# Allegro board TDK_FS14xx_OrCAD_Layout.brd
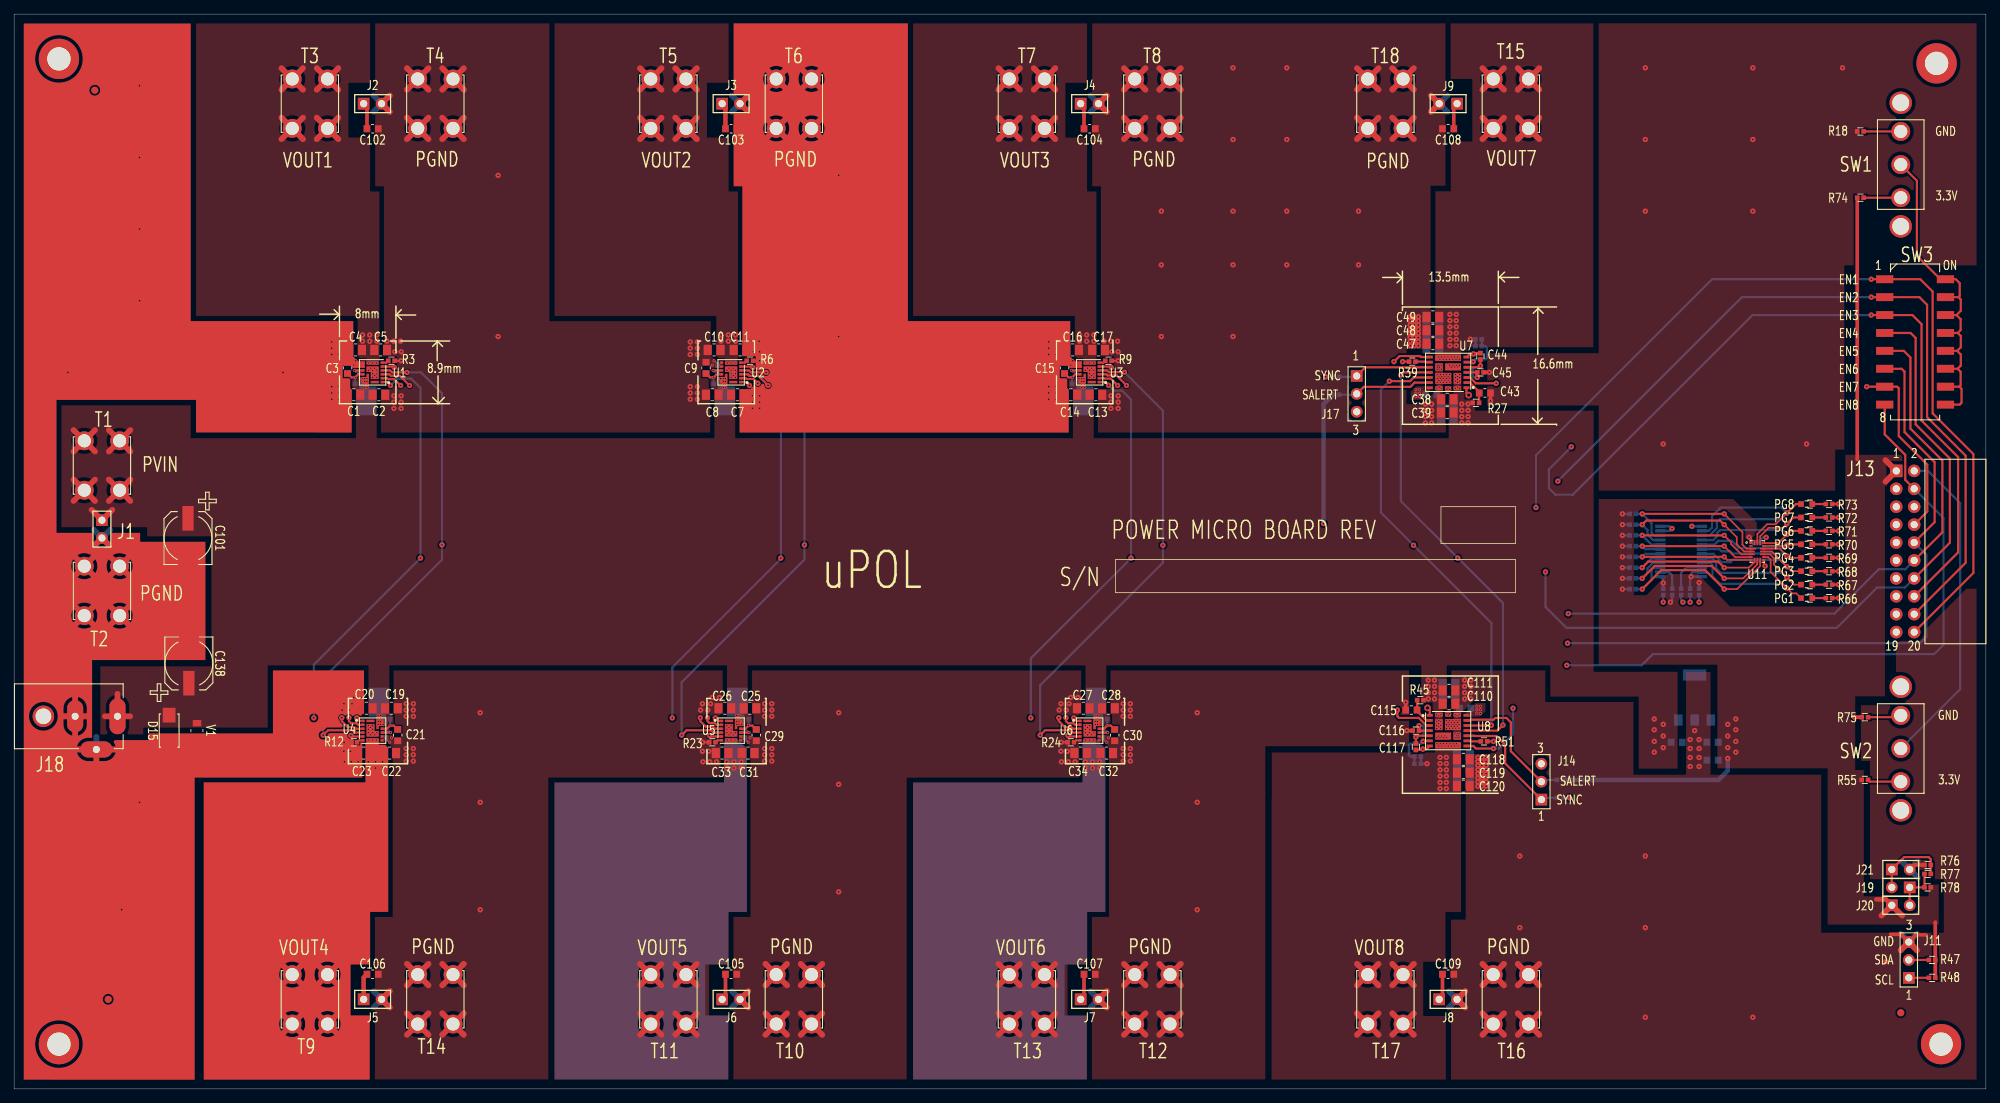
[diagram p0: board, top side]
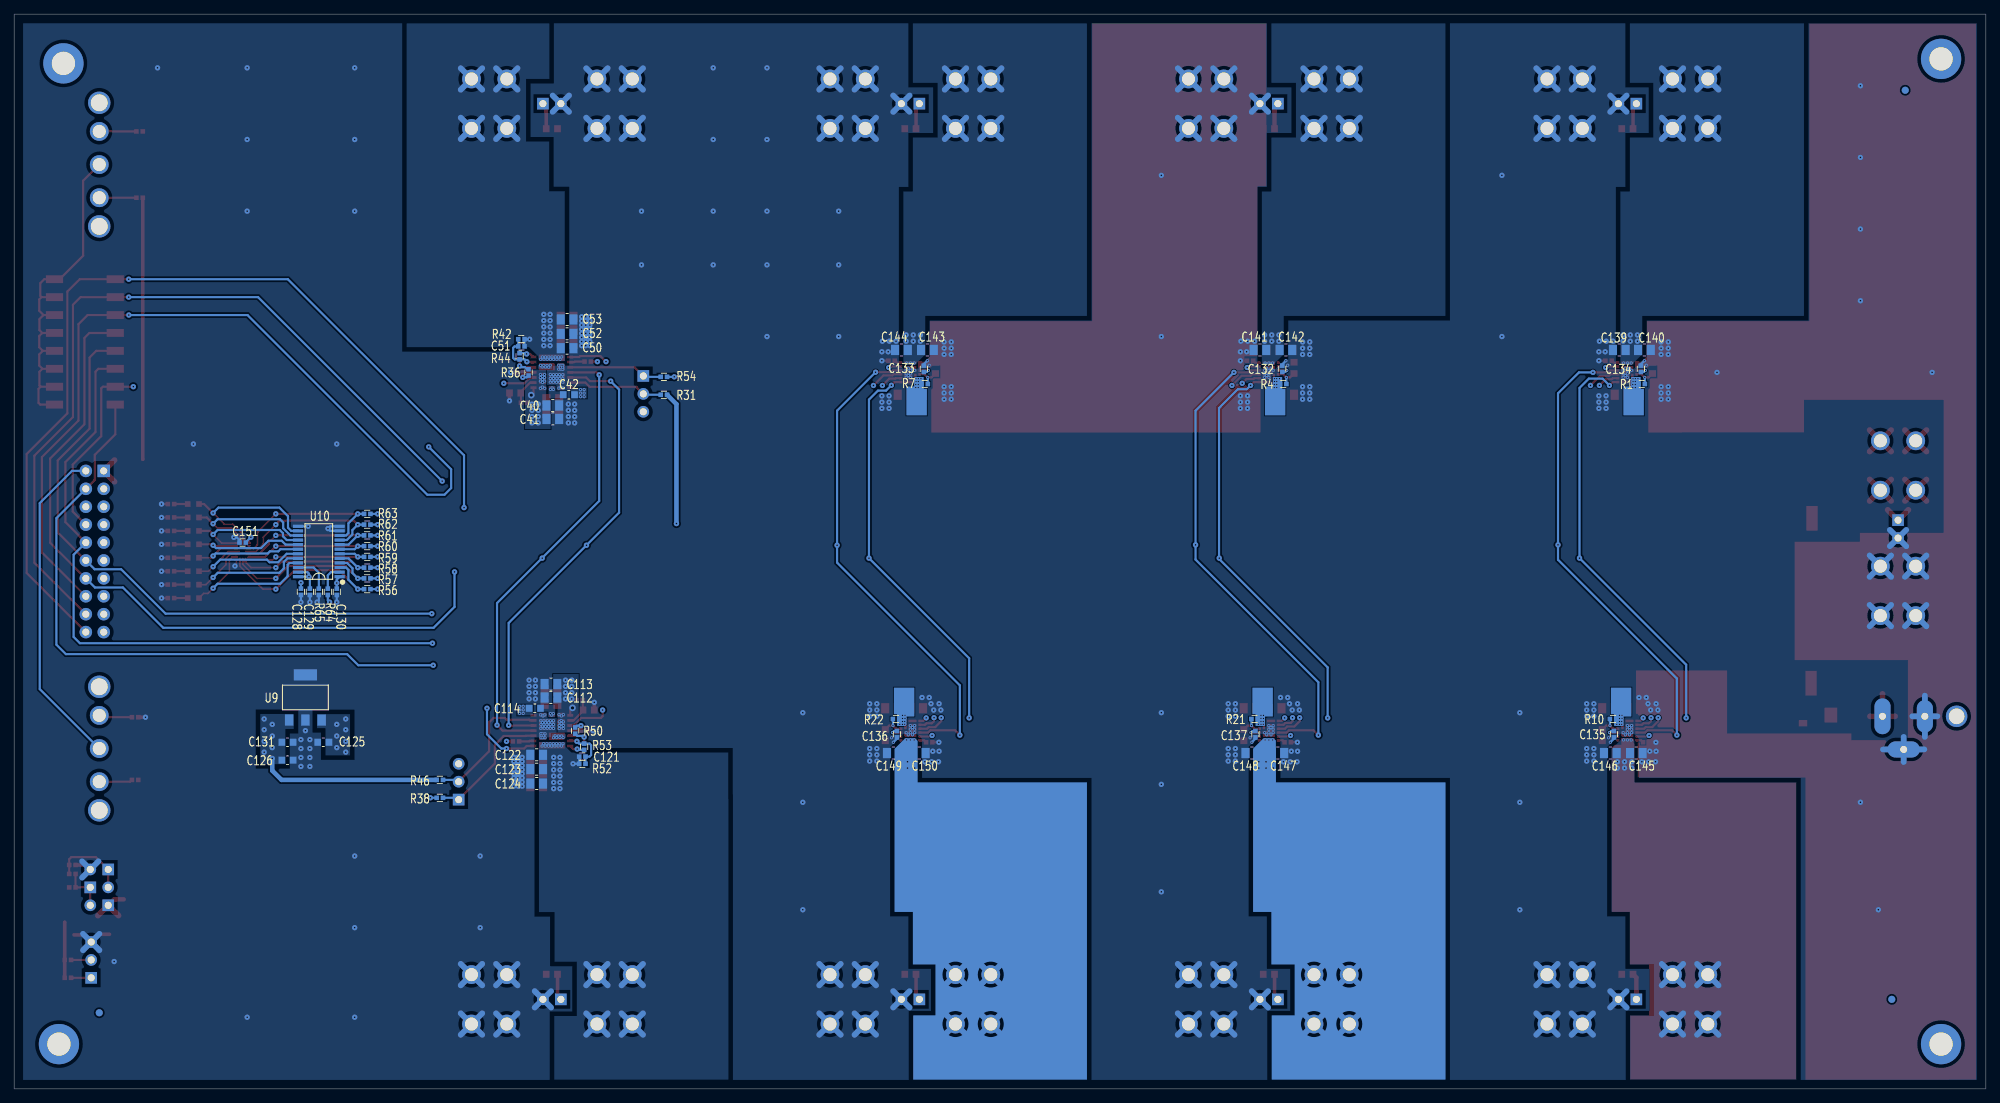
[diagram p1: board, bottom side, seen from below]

Outline 279.4 x 152.4 mm; copper layers: TOP, L2, L3, BOTTOM. Coordinates in mm from the lower left corner of the outline.
Outline path: 0,152.4 0,0 279.4,0 279.4,152.4 0,152.4

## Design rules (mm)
constraint set DEFAULT: min track width 0.305

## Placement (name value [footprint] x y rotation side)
C1  22uF  [0805]  48.13 98.42 0 top
C2  22uF  [0805]  51.69 98.42 180 top
C3  1uF  [0603]  47.24 102.23 270 top
C4  47uF  [0805]  48.39 104.78 180 top
C5  47uF  [0805]  51.94 104.78 0 top
C7  22uF  [0805]  102.49 98.42 180 top
C8  22uF  [0805]  98.93 98.42 0 top
C9  1uF  [0603]  98.04 102.23 270 top
C10  22uF  [0805]  99.19 104.78 180 top
C11  22uF  [0805]  102.87 104.78 0 top
C13  22uF  [0805]  153.29 98.42 180 top
C14  22uF  [0805]  149.73 98.42 0 top
C15  1uF  [0603]  148.84 102.23 270 top
C16  22uF  [0805]  149.99 104.78 180 top
C17  22uF  [0805]  153.67 104.78 0 top
C19  22uF  [0805]  53.47 53.98 180 top
C20  22uF  [0805]  49.91 53.98 0 top
C21  1uF  [0603]  54.36 50.16 90 top
C22  22uF  [0805]  53.21 47.62 0 top
C23  22uF  [0805]  49.53 47.62 180 top
C25  22uF  [0805]  104.27 53.98 180 top
C26  22uF  [0805]  100.71 53.98 0 top
C27  22uF  [0805]  151.51 53.98 0 top
C28  22uF  [0805]  155.07 53.98 180 top
C29  1uF  [0603]  105.16 50.16 90 top
C30  1uF  [0603]  155.96 50.16 90 top
C31  22uF  [0805]  104.01 47.62 0 top
C32  47uF  [0805]  154.81 47.62 0 top
C33  22uF  [0805]  100.33 47.62 180 top
C34  47uF  [0805]  151.13 47.62 180 top
C38  N/S  [0805]  203.07 97.79 0 top
C39  22uF  [0805]  203.07 95.89 0 top
C40  22uF  [0805]  203.07 96.9 0 bottom
C41  22uF  [0805]  203.07 95 0 bottom
C42  2.2uF/16V_N/S  [0603]  200.79 98.42 0 bottom
C43  1uF  [0603]  208.41 98.68 180 top
C44  2.2uF  [0402]  207.77 103.89 270 top
C45  2.2uF  [0402]  207.77 101.6 180 top
C47  N/S  [0805]  201.04 105.66 180 top
C48  N/S  [0805]  201.04 107.57 180 top
C49  N/S  [0805]  201.04 109.47 180 top
C50  N/S  [0805]  201.04 105.03 180 bottom
C51  N/S  [0402]  207.52 105.28 0 bottom
C52  47uF  [0805]  201.04 107.06 180 bottom
C53  47uF  [0805]  201.04 109.09 180 bottom
C101  180uF  [C10_CAP]  24.64 78.11 270 top
C102  1uF  [0603]  50.8 136.14 180 top
C103  1uF  [0603]  101.6 136.14 180 top
C104  1uF  [0603]  152.4 136.14 180 top
C105  1uF  [0603]  101.6 16.26 180 top
C106  1uF  [0603]  50.8 16.26 180 top
C107  1uF  [0603]  152.4 16.26 180 top
C108  1uF  [0603]  203.2 136.14 0 top
C109  1uF  [0603]  203.2 16.26 180 top
C110  N/S  [0805]  203.33 54.61 180 top
C111  22uF  [0805]  203.33 56.52 180 top
C112  22uF  [0805]  203.33 55.5 180 bottom
C113  22uF  [0805]  203.33 57.4 180 bottom
C114  2.2uF/16V_N/S  [0603]  205.61 53.98 180 bottom
C115  1uF  [0603]  197.99 53.72 0 top
C116  2.2uF  [0402]  198.63 50.8 0 top
C117  2.2uF  [0402]  198.63 48.51 90 top
C118  N/S  [0805]  205.36 46.74 0 top
C119  N/S  [0805]  205.36 44.83 0 top
C120  N/S  [0805]  205.36 42.93 0 top
C121  N/S  [0402]  198.88 47.12 180 bottom
C122  N/S  [0805]  205.36 47.37 0 bottom
C123  47uF  [0805]  205.36 45.34 0 bottom
C124  47uF  [0805]  205.36 43.31 0 bottom
C125  1uF  [0603]  235.59 49.15 180 bottom
C126  1uF  [0603]  240.66 46.61 0 bottom
C128  0.1uF  [0402]  238.76 70.48 90 bottom
C129  0.1uF  [0402]  237.49 70.48 90 bottom
C130  0.1uF  [0402]  233.68 70.48 90 bottom
C131  4.7uF  [0603]  240.66 49.15 0 bottom
C132  N/S  [0402]  99.69 102.11 270 bottom
C133  N/S  [0402]  150.5 102.11 270 bottom
C134  N/S  [0402]  48.9 102.11 270 bottom
C135  N/S  [0402]  52.7 50.29 90 bottom
C136  N/S  [0402]  154.31 50.29 90 bottom
C137  N/S  [0402]  103.5 50.29 90 bottom
C138  180uF  [C10_CAP]  24.77 60.33 90 top
C139  47uF  [0805]  51.94 104.78 0 bottom
C140  22uF  [0805]  48.39 104.78 180 bottom
C141  22uF  [0805]  102.87 104.78 0 bottom
C142  22uF  [0805]  99.19 104.78 180 bottom
C143  22uF  [0805]  149.99 104.78 180 bottom
C144  22uF  [0805]  153.67 104.78 0 bottom
C145  N/S  [0805]  49.53 47.62 180 bottom
C146  22uF  [0805]  53.21 47.62 0 bottom
C147  N/S  [0805]  100.33 47.62 180 bottom
C148  22uF  [0805]  104.01 47.62 0 bottom
C149  47uF  [0805]  154.81 47.62 0 bottom
C150  22uF  [0805]  151.13 47.62 180 bottom
C151  1uF  [0402]  247.01 77.47 0 bottom
D1  GREEN  [SML-LX0603]  254 69.6 180 top
D2  GREEN  [SML-LX0603]  254 71.5 180 top
D3  GREEN  [SML-LX0603]  254 73.41 180 top
D4  GREEN  [SML-LX0603]  254 75.31 180 top
D5  GREEN  [SML-LX0603]  254 77.22 180 top
D6  GREEN  [SML-LX0603]  254 79.12 180 top
D7  GREEN  [SML-LX0603]  254 81.03 180 top
D8  GREEN  [SML-LX0603]  254 82.93 180 top
D15  -  [DO-214AC_BI]  21.97 50.8 270 top
J1  -  [HDR1X2]  12.45 79.38 270 top
J2  -  [HDR1X2]  50.8 139.7 0 top
J3  -  [HDR1X2]  101.6 139.7 0 top
J4  -  [HDR1X2]  152.4 139.7 0 top
J5  -  [HDR1X2]  50.8 12.7 0 top
J6  -  [HDR1X2]  101.6 12.7 0 top
J7  -  [HDR1X2]  152.4 12.7 0 top
J8  -  [HDR1X2]  203.2 12.7 0 top
J9  -  [HDR1X2]  203.2 139.7 180 top
J11  -  [HDR1X3]  268.48 18.29 90 top
J13  -  [SSQ-110-02-T-D-RA]  267.97 76.2 270 top
J14  -  [HDR1X3]  216.41 43.56 90 top
J17  -  [HDR1X3]  190.25 98.55 270 top
J18  -  [PJ-058A]  11.65 52.83 270 top
J19  -  [HDR1X2]  267.33 26.04 0 top
J20  -  [HDR1X2]  267.33 28.57 180 top
J21  -  [HDR1X2]  267.33 31.11 0 top
NOREF  -  []  58.9 -20.95 0 top
NOREF#2  -  []  289.56 152.4 0 top
NOREF#3  -  [unnamed#2]  13.34 12.7 0 top
NOREF#4  -  []  0 0 270 top
NOREF#5  -  []  204.53 47.88 0 top
NOREF#6  -  [unnamed#2]  267.33 10.79 0 top
NOREF#7  -  []  99.19 103.89 0 top
NOREF#8  -  [unnamed#2]  272.42 145.41 0 top
NOREF#9  -  []  0 0 0 top
NOREF#10  -  []  0 0 0 top
NOREF#11  -  []  0 0 90 top
NOREF#12  -  []  48.03 103.89 0 top
NOREF#13  -  []  289.56 0 0 top
NOREF#14  -  []  -10.16 0 0 top
NOREF#15  -  []  0 152.4 180 top
NOREF#16  -  []  279.4 0 0 top
NOREF#17  -  []  0 0 0 top
NOREF#18  -  []  279.4 152.4 90 top
NOREF#19  -  [unnamed#2]  6.35 6.35 0 top
NOREF#20  -  []  -300.74 386.97 0 top
NOREF#21  -  []  104.17 48.26 0 top
NOREF#22  -  []  154.37 48.26 0 top
NOREF#23  -  []  149.78 103.89 0 top
NOREF#24  -  []  205.74 104.3 0 top
NOREF#25  -  [unnamed#2]  273.05 6.35 0 top
NOREF#26  -  [unnamed#2]  11.43 141.6 0 top
NOREF#27  -  []  53.64 48.26 0 top
NOREF#28  -  [unnamed#2]  6.35 146.05 0 top
NOREF#29  -  []  0 0 0 top
NOREF#30  -  []  -164.59 -61.47 0 top
NOREF#31  -  []  0 0 90 top
NOREF#32  -  []  -205.49 -126.87 0 top
NOREF#33  -  []  86.08 -39.5 0 top
NOREF#34  -  [unnamed#2]  267.33 10.79 180 bottom
NOREF#35  -  [unnamed#2]  13.34 12.7 180 bottom
NOREF#36  -  [unnamed#2]  11.43 141.6 180 bottom
R1  2.7ohm  [0402]  48.77 99.95 0 bottom
R3  0  [0402]  53.47 103.25 180 top
R4  2.7ohm  [0402]  99.57 99.95 0 bottom
R6  10K  [0402]  104.27 103.25 180 top
R7  2.7ohm  [0402]  150.37 99.95 0 bottom
R9  20K  [0402]  155.07 103.25 180 top
R10  2.7ohm  [0402]  52.83 52.45 180 bottom
R12  49.9K  [0402]  48.13 49.15 0 top
R18  10K  [0402]  261.62 135.76 180 top
R21  2.7ohm  [0402]  103.63 52.45 180 bottom
R22  2.7ohm  [0402]  154.43 52.45 180 bottom
R23  49.9K  [0402]  98.93 49.15 0 top
R24  0  [0402]  149.73 49.15 0 top
R27  2.7ohm  [0402]  207.14 97.28 0 top
R31  4.99K  [0402]  187.32 98.42 180 bottom
R36  0  [0402]  206.5 101.6 270 bottom
R38  10K  [0402]  219.07 41.27 0 bottom
R39  0  [0402]  198.12 103.12 180 top
R42  0  [0402]  207.52 106.3 0 bottom
R44  N/S  [0402]  207.77 103.89 270 bottom
R45  2.7ohm  [0402]  199.26 55.12 180 top
R46  4.99K  [0402]  219.07 43.81 0 bottom
R47  4.99K  [0402]  271.78 18.29 0 top
R48  4.99K  [0402]  271.78 15.75 0 top
R50  0  [0402]  199.9 50.8 90 bottom
R51  0  [0402]  208.28 49.28 0 top
R52  0  [0402]  198.88 46.1 180 bottom
R53  N/S  [0402]  198.63 48.51 90 bottom
R54  10K  [0402]  187.32 100.97 180 bottom
R55  10K  [0402]  262.25 43.81 180 top
R56  49.9K  [0402]  229.36 70.87 180 bottom
R57  49.9K  [0402]  229.36 72.39 180 bottom
R58  49.9K  [0402]  229.36 73.91 0 bottom
R59  49.9K  [0402]  229.36 75.44 180 bottom
R60  49.9K  [0402]  229.36 76.96 180 bottom
R61  49.9K  [0402]  229.36 78.49 180 bottom
R62  49.9K  [0402]  229.36 80.01 0 bottom
R63  49.9K  [0402]  229.36 81.53 180 bottom
R64  10K  [0402]  234.95 70.48 270 bottom
R65  1k  [0402]  236.22 70.48 90 bottom
R66  261  [0402]  257.18 69.6 180 top
R67  261  [0402]  257.18 71.5 180 top
R68  261  [0402]  257.18 73.41 180 top
R69  261  [0402]  257.18 75.31 180 top
R70  261  [0402]  257.18 77.22 180 top
R71  261  [0402]  257.18 79.12 180 top
R72  261  [0402]  257.18 81.03 180 top
R73  261  [0402]  257.18 82.93 180 top
R74  10K  [0402]  261.62 126.36 180 top
R75  10K  [0402]  262.25 52.7 180 top
R76  10K  [0402]  271.14 31.75 180 top
R77  15K  [0402]  271.14 30.48 0 top
R78  15K  [0402]  271.14 28.57 180 top
SW1  -  [1101M1S3CQE2]  267.33 131.06 0 top
SW2  -  [1101M1S3CQE2]  267.33 48.26 0 top
SW3  -  [219-8MST]  269.37 105.92 270 top
T1  -  [7693]  12.45 88.39 0 top
T2  -  [7693]  12.45 70.61 0 top
T3  -  [7693]  41.91 139.7 0 top
T4  -  [7693]  59.69 139.7 0 top
T5  -  [7693]  92.71 139.7 0 top
T6  -  [7693]  110.49 139.7 0 top
T7  -  [7693]  143.51 139.7 0 top
T8  -  [7693]  161.29 139.7 0 top
T9  -  [7693]  41.91 12.7 0 top
T10  -  [7693]  110.49 12.7 0 top
T11  -  [7693]  92.71 12.7 0 top
T12  -  [7693]  161.29 12.7 0 top
T13  -  [7693]  143.51 12.7 0 top
T14  -  [7693]  59.69 12.7 0 top
T15  -  [7693]  212.09 139.7 0 top
T16  -  [7693]  212.09 12.7 0 top
T17  -  [7693]  194.31 12.7 0 top
T18  -  [7693]  194.31 139.7 0 top
U1  -  [FS1406-02_NEW]  50.8 101.6 180 top
U2  -  [FS1406-02_NEW]  101.6 101.6 180 top
U3  -  [FS1406-02_NEW]  152.4 101.6 180 top
U4  -  [FS1406-02_NEW]  50.8 50.8 0 top
U5  -  [FS1406-02_NEW]  101.6 50.8 0 top
U6  -  [FS1406-02_NEW]  152.4 50.8 0 top
U7  -  [FS1412-POD]  203.2 101.6 180 top
U8  -  [FS1412-POD]  203.2 50.8 0 top
U9  -  [SOT223]  238.12 55.5 180 bottom
U10  -  [SOP65P640X120-24N]  236.22 76.2 90 bottom
U11  -  [STQFN20]  247.01 76.2 0 top
V1  -  [AVR]  25.91 50.8 270 top

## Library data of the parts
C1 C2 C4 C5 C7 C8 C10 C11 C13 C14 C16 C17 C19 C20 C22 C23 C25-C28 C31-C34 C38-C41 C47-C50 C52 C53 C110-C113 C118-C120 C122-C124 C139-C150 = 0805
C3 C9 C15 C21 C29 C30 C42 C43 C102-C109 C114 C115 C125 C126 C131 = 0603
C44 C45 C51 C116 C117 C121 C128-C130 C132-C137 C151 R1 R3 R4 R6 R7 R9 R10 R12 R18 R21-R24 R27 R31 R36 R38 R39 R42 R44-R48 R50-R78 = 0402
C101 C138 = C10_CAP
D1-D8 = SML-LX0603
D15 = SMAJ17CA
J1-J9 J19-J21 = HDR1X2
J11 J14 J17 = HDR1X3
J13 = SSQ-110-02-T-D-RA
J18 = PJ-058A
SW1 SW2 = 1101M1S3CQE2
SW3 = 219-8MST
T1-T18 = 7693
U1-U6 = FS1406-02_NEW
U7 = FS1412
U8 = FS1408
U9 = ZSR330GTA
U10 = SN74AVC8T245
U11 = STQFN20
V1 = AVR

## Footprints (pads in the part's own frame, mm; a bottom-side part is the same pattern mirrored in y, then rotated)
219-8MST
  rect 1.118x2.438 smd: 1(-8.89,-4.305) 2(-6.35,-4.305) 3(-3.81,-4.305) 4(-1.27,-4.305) 5(1.27,-4.305) 6(3.81,-4.305) 7(6.35,-4.305) 8(8.89,-4.305) 9(8.89,4.305) 10(6.35,4.305) 11(3.81,4.305) 12(1.27,4.305) 13(-1.27,4.305) 14(-3.81,4.305) 15(-6.35,4.305) 16(-8.89,4.305)
0402
  rect 0.65x0.65 smd: 1(-0.45,0) 2(0.45,0)
0603
  rect 0.95x1.001 smd: 1(-0.8,0) 2(0.8,0)
0805
  rect 1.151x1.45 smd: 1(-0.902,0) 2(0.902,0)
1101M1S3CQE2
  round 2.667 hole 1.854: 1(0,-4.699) 2(0,0) 3(0,4.699)
  round 3.175 hole 2.388: SH1(0,8.763) SH2(0,-8.763)
7693
  round 2.667 hole 1.854: 1(-2.502,3.505) 2(-2.502,-3.505) 3(2.502,-3.505) 4(2.502,3.505)
AVR
  rect 0.899x1.199 smd: 1(-1.049,0) 2(1.049,0)
C10_CAP
  rect 3.5x1.6 smd: 1(-2.799,0) 2(2.799,0)
DO-214AC_BI
  rect 2.101x1.801 smd: 1(2.2,0) 2(-2.2,0)
FS1406-02_NEW
  rect 0.45x0.351 smd: 1(-1.349,1.374) 2(-1.349,0.826) 3(-1.349,0.274) 4(-1.349,-0.274) 5(-1.349,-0.826) 6(-1.349,-1.374) 8(1.349,-1.374) 9(1.349,-0.826) 10(1.349,-0.274) 11(1.349,0.274)
  rect 1.75x0.45 smd: 7(0,-1.326)
  rect 0.201x0.201 smd: 12(0.8,1.3) 13(1.3,1.3) 14(0.8,0.899) 16(0,0) 17(1.3,0.899)
  rect 1.151x0.351 smd: 15(-0.3,1.374)
FS1412-POD
  rect 0.851x0.399 smd: 1(-2.601,2.174) 2(-2.601,1.45) 3(-2.601,0.724) 4(-2.601,0) 5(-2.601,-0.724) 6(-2.601,-1.45) 7(-2.601,-2.174) 9(2.601,-2.174) 10(2.601,-1.45) 11(2.601,-0.724) 12(2.601,0) 13(2.601,0.724) 14(2.601,1.45) 15(2.601,2.174)
  rect 3.65x0.899 smd: 8(0,-2.075)
  rect 1.049x0.551 smd: 16(1.3,2.25) 18(-1.3,2.25)
  rect 0.851x0.551 smd: 17(0,2.25)
  rect 1.049x1.549 smd: 19(-1.3,0.851)
  rect 1.049x1.001 smd: 20(1.3,-0.775)
  rect 2.25x1.549 smd: 21(0.701,0.851)
  rect 2.25x1.001 smd: 22(-0.701,-0.775)
HDR1X2
  rect 1.651x1.651 hole 1.016: 1(-1.27,0)
  round 1.651 hole 1.016: 2(1.27,0)
HDR1X3
  rect 1.651x1.651 hole 1.016: 1(-2.54,0)
  round 1.651 hole 1.016: 2(0,0) 3(2.54,0)
PJ-058A
  round 3.048 hole 2.21: (0,-7.501)
  oval 5.08x2.286 hole 0.991: 1(0,3)
  oval 4.572x2.286 hole 0.991: 2(0,-3)
  oval 2.286x4.572 hole 0.991: 3(4.699,0)
SML-LX0603
  rect 0.8x0.8 smd: 1(0.8,0) 2(-0.8,0)
SOP65P640X120-24N
  rect 0.457x1.448 smd: 1(-3.574,-2.949) 2(-2.926,-2.949) 3(-2.276,-2.949) 4(-1.626,-2.949) 5(-0.975,-2.949) 6(-0.325,-2.949) 7(0.325,-2.949) 8(0.975,-2.949) 9(1.626,-2.949) 10(2.276,-2.949) 11(2.926,-2.949) 12(3.574,-2.949) 13(3.574,2.949) 14(2.926,2.949) 15(2.276,2.949) 16(1.626,2.949) 17(0.975,2.949) 18(0.325,2.949) 19(-0.325,2.949) 20(-0.975,2.949) 21(-1.626,2.949) 22(-2.276,2.949) 23(-2.926,2.949) 24(-3.574,2.949)
SOT223
  rect 1.199x1.6 smd: 1(-2.301,-3.2) 2(0,-3.2) 3(2.301,-3.2)
  rect 3.299x1.6 smd: 4(0,3.2)
SSQ-110-02-T-D-RA
  rect 1.778x1.778 hole 1.016: 1(-11.43,-1.27)
  round 1.778 hole 1.016: 2(-11.43,1.27) 3(-8.89,-1.27) 4(-8.89,1.27) 5(-6.35,-1.27) 6(-6.35,1.27) 7(-3.81,-1.27) 8(-3.81,1.27) 9(-1.27,-1.27) 10(-1.27,1.27) 11(1.27,-1.27) 12(1.27,1.27) 13(3.81,-1.27) 14(3.81,1.27) 15(6.35,-1.27) 16(6.35,1.27) 17(8.89,-1.27) 18(8.89,1.27) 19(11.43,-1.27) 20(11.43,1.27)
STQFN20
  rect 0.485x0.231 smd: 1(-0.907,1.199) 2(-0.907,0.8) 6(-0.907,-0.8) 7(-0.907,-1.199) 11(0.907,-1.199) 12(0.907,-0.8) 16(0.907,0.8) 17(0.907,1.199)
  rect 0.975x0.231 smd: 3(-0.663,0.399)
  rect 0.775x0.231 smd: 4(-0.762,0) 5(-0.762,-0.399) 13(0.762,-0.399) 14(0.762,0) 15(0.762,0.399)
  rect 0.231x0.775 smd: 8(-0.399,-1.262) 9(0,-1.262) 10(0.399,-1.262) 18(0.399,1.262) 19(0,1.262) 20(-0.399,1.262)
unnamed#2
  round 1.016 smd: (0,0)

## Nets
3.3V: C126.2 C128.2 C129.2 C130.2 C131.2 C151.1 J13.1 J19.1 R31.2 R46.2 R47.2 R48.2 R55.2 R56.2 R57.2 R58.1 R59.2 R60.2 R61.2 R62.1 R63.2 R64.2 R74.2 R78.1 U9.1 U10.1 U10.23 U10.24 U11.1
AGND1: C44.1 J17.3 R39.2 R44.1 R54.2 U7.7 U7.22
AGND2: C117.1 J14.3 R38.2 R51.2 R53.1 U8.7 U8.22
PGND: C1.1 C2.1 C3.1 C4.2 C5.2 C7.1 C8.1 C9.1 C10.2 C11.2 C13.1 C14.1 C15.1 C16.2 C17.2 C19.1 C20.1 C21.1 C22.2 C23.2 C25.1 C26.1 C27.1 C28.1 C29.1 C30.1 C31.2 C32.2 C33.2 C34.2 C38.1 C39.1 C40.1 C41.1 C43.1 C45.1 C47.2 C48.2 C49.2 C50.2 C52.2 C53.2 C101.2 C102.1 C103.1 C104.1 C105.1 C106.1 C107.1 C108.1 C109.1 C110.1 C111.1 C112.1 C113.1 C115.1 C116.1 C118.2 C119.2 C120.2 C122.2 C123.2 C124.2 C125.1 C126.1 C128.1 C129.1 C130.1 C131.1 C132.1 C133.1 C134.1 C135.1 C136.1 C137.1 C138.2 C139.2 C140.2 C141.2 C142.2 C143.2 C144.2 C145.2 C146.2 C147.2 C148.2 C149.2 C150.2 C151.2 D15.1 J1.2 J2.2 J3.2 J4.2 J5.2 J6.2 J7.2 J8.2 J9.2 J11.3 J13.11 J18.2 J18.3 J21.2 R3.1 R6.1 R9.1 R12.1 R18.2 R23.1 R24.1 R65.1 R66.1 R67.1 R68.1 R69.1 R70.1 R71.1 R72.1 R73.1 R75.2 R76.2 T2.1 T2.2 T2.3 T2.4 T4.1 T4.2 T4.3 T4.4 T6.1 T6.2 T6.3 T6.4 T8.1 T8.2 T8.3 T8.4 T10.1 T10.2 T10.3 T10.4 T12.1 T12.2 T12.3 T12.4 T14.1 T14.2 T14.3 T14.4 T16.1 T16.2 T16.3 T16.4 T18.1 T18.2 T18.3 T18.4 U1.8 U1.9 U1.16 U2.8 U2.9 U2.16 U3.8 U3.9 U3.16 U4.8 U4.9 U4.16 U5.8 U5.9 U5.16 U6.8 U6.9 U6.16 U7.16 U7.20 U7.21 U8.16 U8.20 U8.21 U9.2 U9.4 U10.11 U10.12 U10.13 U11.11 V1.2
PVIN: C1.2 C2.2 C7.2 C8.2 C13.2 C14.2 C19.2 C20.2 C25.2 C26.2 C27.2 C28.2 C38.2 C39.2 C40.2 C41.2 C101.1 C110.2 C111.2 C112.2 C113.2 C125.2 C138.1 D15.2 J1.1 J18.1 R1.2 R4.2 R7.2 R10.2 R21.2 R22.2 R27.1 R45.1 T1.1 T1.2 T1.3 T1.4 U1.12 U1.13 U1.14 U1.17 U2.12 U2.13 U2.14 U2.17 U3.12 U3.13 U3.14 U3.17 U4.12 U4.13 U4.14 U4.17 U5.12 U5.13 U5.14 U5.17 U6.12 U6.13 U6.14 U6.17 U7.18 U7.19 U8.18 U8.19 U9.3 V1.1
VCC3: C133.2 U3.10
CTRL: J13.2 SW2.2
EN1: J13.20 SW3.1 U1.3
EN2: J13.18 SW3.2 U2.3
EN3: J13.16 SW3.3 U3.3
EN4: J13.14 SW3.4 U4.3
EN5: J13.12 SW3.5 U5.3
EN6: J13.10 SW3.6 U6.3
EN7: J13.8 SW3.7 U7.3
EN8: J13.4 SW3.8 U8.3
LED1: D1.1 U10.21 U11.12
LED2: D2.1 U10.20 U11.13
LED3: D3.1 U10.19 U11.14
LED4: D4.1 U10.18 U11.15
LED5: D5.1 U10.17 U11.16
LED6: D6.1 U10.16 U11.17
LED7: D7.1 U10.15 U11.18
LED8: D8.1 U10.14 U11.19
OPT: J13.6 J20.2 J21.1 R76.1 R77.2
PGOOD1: J13.19 R56.1 U1.2 U10.3 U11.10
PGOOD2: J13.17 R57.1 U2.2 U10.4 U11.9
PGOOD3: J13.15 R58.2 U3.2 U10.5 U11.8
PGOOD4: J13.13 R59.1 U4.2 U10.6 U11.7
PGOOD5: J13.9 R60.1 U5.2 U10.7 U11.6
PGOOD6: J13.7 R61.1 U6.2 U10.8 U11.5
PGOOD7: J13.5 R62.2 U7.9 U10.9 U11.4
PGOOD8: J13.3 R63.1 U8.9 U10.10 U11.3
SALERT7: J17.2 R31.1 U7.14
SALERT8: J14.2 R46.1 U8.14
SCL: J11.1 R48.1 U1.4 U2.4 U3.4 U4.4 U5.4 U6.4 U7.13 U8.13
SDA: J11.2 R47.1 U1.1 U2.1 U3.1 U4.1 U5.1 U6.1 U7.12 U8.12
SYNC7: J17.1 R54.1 U7.11
SYNC8: J14.1 R38.1 U8.11
VOUT1: C4.1 C5.1 C102.2 C139.1 C140.1 J2.1 T3.1 T3.2 T3.3 T3.4 U1.5 U1.7
VOUT2: C10.1 C11.1 C103.2 C141.1 C142.1 J3.1 T5.1 T5.2 T5.3 T5.4 U2.5 U2.7
VOUT3: C16.1 C17.1 C104.2 C143.1 C144.1 J4.1 T7.1 T7.2 T7.3 T7.4 U3.5 U3.7
VOUT4: C22.1 C23.1 C106.2 C145.1 C146.1 J5.1 T9.1 T9.2 T9.3 T9.4 U4.5 U4.7
VOUT5: C31.1 C33.1 C105.2 C147.1 C148.1 J6.1 T11.1 T11.2 T11.3 T11.4 U5.5 U5.7
VOUT6: C32.1 C34.1 C107.2 C149.1 C150.1 J7.1 T13.1 T13.2 T13.3 T13.4 U6.5 U6.7
VOUT7: C47.1 C48.1 C49.1 C50.1 C51.1 C52.1 C53.1 C108.2 J9.1 R42.1 T15.1 T15.2 T15.3 T15.4 U7.8
VOUT8: C109.2 C118.1 C119.1 C120.1 C121.1 C122.1 C123.1 C124.1 J8.1 R52.1 T17.1 T17.2 T17.3 T17.4 U8.8
N106541: C9.2 R4.1 U2.11
N109036: C132.2 U2.10
N111800: C15.2 R7.1 U3.11
N112773: C3.2 R1.1 U1.11
N113813: C21.2 R10.1 U4.11
N124020: R6.2 U2.6
N125365: R3.2 U1.6
N125599: R12.2 U4.6
N125833: R9.2 U3.6
N143732: C29.2 R21.1 U5.11
N143740: C30.2 R22.1 U6.11
N143880: R23.2 U5.6
N143888: R24.2 U6.6
N983153: C42.2 U7.17
N983255: C42.1 U7.15
N983335: C43.2 R27.2 U7.2
N983701: C45.2 R36.2 U7.4
N983781: C44.2 R36.1 U7.5
N983905: R39.1 U7.10
N983923: C51.2 R42.2 R44.2 U7.6
N1133327: C114.2 U8.17
N1133411: C114.1 U8.15
N1133439: C115.2 R45.2 U8.2
N1133683: C116.2 R50.2 U8.4
N1133735: C117.2 R50.1 U8.5
N1133791: R51.1 U8.10
N1133799: C121.2 R52.2 R53.2 U8.6
N1144589: SW1.2 SW3.9 SW3.10 SW3.11 SW3.12 SW3.13 SW3.14 SW3.15 SW3.16
N1166950: R75.1 SW2.3
N1167645: R55.1 SW2.1
N1170426: R64.1 U10.2
N1170926: D4.2 R69.2
N1170982: D5.2 R70.2
N1171050: D6.2 R71.2
N1171118: D7.2 R72.2
N1171178: D8.2 R73.2
N1171210: R65.2 U10.22
N1176310: D3.2 R68.2
N1183669: D1.2 R66.2
N1183969: D2.2 R67.2
N1197737: R74.1 SW1.1
N1197747: R18.1 SW1.3
N1234759: C134.2 U1.10
N1235035: C135.2 U4.10
N1235784: C136.2 U6.10
N1236304: C137.2 U5.10
N1413705: J19.2 J20.1 R77.1 R78.2

Pads without a net: SW1 SH1 SH2; SW2 SH1 SH2; U1 15; U2 15; U3 15; U4 15; U5 15; U6 15; U7 1; U8 1; U11 2 20

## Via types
v1: diameter 0.457, hole 0.203, TOP to BOTTOM, 308 vias
v2: diameter 0.762, hole 0.254, TOP to BOTTOM, 493 vias
v3: diameter 0.95, hole 0.475, TOP to BOTTOM, 2 vias

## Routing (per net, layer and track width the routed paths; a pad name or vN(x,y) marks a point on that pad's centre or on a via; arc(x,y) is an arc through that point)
3.3V: length 162.7
  TOP w0.305: v2(245.85,78.23) 246.11,77.97 U11.1
  TOP w0.508: 272.24,23.62 272.23,23.61 R47.2 R48.2 ; 261.16,89.28 261.17,89.29 R74.2
  TOP w0.635: J19.1 265.23,26.87 263.88,26.87
  TOP w0.813: 267.53,24.57 J19.1 264.6,24.57 ; 265.17,86.1 J13.1 265.17,89.16
  L3 w0.635: v2(185.55,80.16) 219.96,80.16 221.64,78.49 v2(227.9,78.49)
  BOTTOM w0.305: C130.2 v2(233.68,71.73) 233.68,72.22 U10.1 ; R58.1 v2(227.9,73.91) ; R61.2 v2(227.9,78.49) ; R64.2 234.95,69.27 v2(234.7,69.02) ; R59.2 v2(227.9,75.44) ; v2(237.62,72.63) 237.49,72.5 C129.2 ; v2(237.62,72.63) 237.62,73.05 237.84,73.27 U10.23 ; v2(237.62,72.63) U10.24 ; R63.2 v2(227.9,81.53) ; R62.1 v2(227.9,80.01) ; C151.1 246.57,77.51 v2(245.85,78.23) ; R60.2 v2(227.9,76.96) ; C128.2 v2(238.76,71.78) ; R56.2 v2(227.9,70.87) ; R57.2 v2(227.9,72.39)
  BOTTOM w0.635: v2(185.55,80.16) 185.55,97.1 R31.2 ; R46.2 241.5,43.81 242.82,45.14 v2(242.82,46.86)
  vias: v2(242.82,51.69) v2(242.82,50.04) v2(242.82,48.39) v2(243.97,52.45) v2(243.97,50.93) v2(243.97,49.28) v2(243.97,47.75)
AGND1: length 18.8
  TOP w0.305: U7.7 205.83,103.77 206.27,104.22 v2(206.78,104.22) 206.9,104.34 C44.1 ; R39.2 v2(196.75,103.12)
  L2 w0.305: 203.23,102.31 202.26,102.31 ; 205.87,103.3 v1(204.8,102.59) 205.82,103.61 ; 203.15,102.57 202.41,102.57 ; 206.12,103.58 v2(206.78,104.22) 205.97,103.91 ; 203.23,102.84 202.39,102.84
  L3 w0.813: J17.3 191.41,97.17 ; J17.3 189.09,97.17 ; J17.3 189.09,94.85 ; J17.3 191.41,94.85
  BOTTOM w0.305: R54.2 v2(185.86,100.97) ; C44.1 206.9,104.34 v2(206.78,104.22)
  vias: v1(203.43,102.62) v1(203.66,102.34) v1(203.89,102.59) v1(204.11,102.36) v1(204.34,102.59) v1(204.57,102.36)
AGND2: length 18.9
  TOP w0.305: U8.7 200.16,48.18 v2(199.62,48.18) 199.5,48.06 C117.1 ; R51.2 v2(209.63,49.28)
  L2 w0.305: 200.56,49.17 v1(201.6,49.81) 200.63,48.82 ; 200.25,48.84 v2(199.62,48.18) 200.33,48.54 ; 203.17,50.29 204.04,50.29 ; 203.12,50.04 204.06,50.04 ; v1(202.97,49.78) 204.14,49.78
  L3 w0.813: 215.25,47.26 J14.3 ; J14.3 217.57,44.94 ; J14.3 217.57,47.26 ; J14.3 215.25,44.94
  BOTTOM w0.305: v2(199.62,48.18) 199.5,48.06 C117.1 ; R38.2 v2(220.41,41.27)
  vias: v1(201.83,50.04) v1(202.06,49.81) v1(202.29,50.04) v1(202.51,49.81) v1(202.74,50.06)
PGND: length 1600.2
  TOP w0.229: U11.11 247.92,74.33 v2(248.11,74.14)
  TOP w0.305: R69.1 v2(258.51,75.31) ; R6.1 v2(105.64,103.25) ; R23.1 v2(97.56,49.15) ; R24.1 v2(148.36,49.15) ; R12.1 v2(46.76,49.15) ; R67.1 v2(258.51,71.5) ; R73.1 v2(258.51,82.93) ; R68.1 v2(258.51,73.41) ; R3.1 v2(54.84,103.25) ; R72.1 v2(258.51,81.03) ; R9.1 v2(156.44,103.25) ; R70.1 v2(258.51,77.22) ; R71.1 v2(258.51,79.12) ; R66.1 v2(258.51,69.6)
  TOP w0.508: R75.2 v2(260.79,52.7) ; R76.2 269.24,31.75 J21.2 ; 265.89,21.92 267.39,21.92 J11.3 269.49,21.84 270.92,21.84 ; C43.1 v2(209.21,97.56) ; C45.1 v2(209.04,101.6) ; C116.1 v2(197.36,50.8) ; C115.1 v2(197.19,54.81)
  TOP w0.813: T12.2 160.31,10.72 ; T12.2 157.27,10.72 ; T12.2 160.31,7.67 ; T12.2 157.27,7.67 ; 111.47,17.73 T10.4 ; T10.4 111.47,14.68 ; T10.4 114.51,17.73 ; T10.4 114.51,14.68 ; T2.2 11.47,68.63 ; T2.2 8.42,68.63 ; T2.2 11.47,65.59 ; T2.2 8.42,65.59 ; T18.2 193.33,137.72 ; T18.2 190.29,134.67 ; T18.2 190.29,137.72 ; T18.2 193.33,134.67 ; 162.27,134.67 T8.3 ; T8.3 165.31,137.72 ; T8.3 165.31,134.67 ; T8.3 162.27,137.72 ; T2.3 16.47,68.63 ; T2.3 13.43,68.63 ; T2.3 16.47,65.59 ; T2.3 13.43,65.59 ; T4.2 58.71,137.72 ; T4.2 55.67,137.72 ; T4.2 55.67,134.67 ; T4.2 58.71,134.67 ; T8.2 160.31,137.72 ; T8.2 157.27,137.72 ; T8.2 157.27,134.67 ; T8.2 160.31,134.67 ; 213.07,14.68 T16.4 ; T16.4 213.07,17.73 ; T16.4 216.11,14.68 ; T16.4 216.11,17.73 ; 55.67,141.68 T4.1 ; T4.1 58.71,144.73 ; T4.1 55.67,144.73 ; T4.1 58.71,141.68 ; 195.29,134.67 T18.3 ; T18.3 198.33,137.72 ; T18.3 198.33,134.67 ; T18.3 195.29,137.72 ; T6.3 114.51,134.67 ; T6.3 111.47,137.72 ; T6.3 114.51,137.72 ; T6.3 111.47,134.67 ; 162.27,10.72 T12.3 ; T12.3 162.27,7.67 ; T12.3 165.31,10.72 ; T12.3 165.31,7.67 ; T2.1 11.47,75.64 ; T2.1 8.42,75.64 ; T2.1 8.42,72.6 ; T2.1 11.47,72.6 ; 106.47,134.67 T6.2 ; T6.2 109.51,134.67 ; T6.2 106.47,137.72 ; T6.2 109.51,137.72 ; 205.63,13.86 J8.2 205.63,11.54 ; 208.07,10.72 T16.2 ; T16.2 211.11,7.67 ; T16.2 208.07,7.67 ; T16.2 211.11,10.72 ; 190.29,144.73 T18.1 ; T18.1 193.33,144.73 ; T18.1 190.29,141.68 ; T18.1 193.33,141.68 ; T16.3 216.11,10.72 ; T16.3 216.11,7.67 ; T16.3 213.07,10.72 ; T16.3 213.07,7.67 ; 157.27,141.68 T8.1 ; T8.1 160.31,141.68 ; T8.1 160.31,144.73 ; T8.1 157.27,144.73 ; T16.1 211.11,14.68 ; T16.1 208.07,14.68 ; T16.1 211.11,17.73 ; T16.1 208.07,17.73 ; J18.3 14.57,48.13 ; J18.3 11.65,46.35 ; J18.3 8.72,48.13 ; T14.1 58.71,14.68 ; T14.1 55.67,17.73 ; T14.1 55.67,14.68 ; T14.1 58.71,17.73 ; 106.47,141.68 T6.1 ; T6.1 106.47,144.73 ; T6.1 109.51,141.68 ; T6.1 109.51,144.73 ; 104.03,13.86 J6.2 104.03,11.54 ; 162.27,141.68 T8.4 ; T8.4 162.27,144.73 ; T8.4 165.31,141.68 ; T8.4 165.31,144.73 ; 60.67,137.72 T4.3 ; T4.3 60.67,134.67 ; T4.3 63.71,134.67 ; T4.3 63.71,137.72 ; 195.29,144.73 T18.4 ; T18.4 198.33,144.73 ; T18.4 195.29,141.68 ; T18.4 198.33,141.68 ; T10.1 109.51,17.73 ; T10.1 106.47,17.73 ; T10.1 106.47,14.68 ; T10.1 109.51,14.68 ; 111.47,7.67 T10.3 ; T10.3 114.51,10.72 ; T10.3 114.51,7.67 ; T10.3 111.47,10.72 ; 162.27,17.73 T12.4 ; T12.4 162.27,14.68 ; T12.4 165.31,14.68 ; T12.4 165.31,17.73 ; 106.47,10.72 T10.2 ; T10.2 106.47,7.67 ; T10.2 109.51,10.72 ; T10.2 109.51,7.67 ; T4.4 63.71,144.73 ; T4.4 60.67,141.68 ; T4.4 63.71,141.68 ; T4.4 60.67,144.73 ; 200.77,138.54 J9.2 200.77,140.86 ; 13.43,75.64 T2.4 ; T2.4 16.47,75.64 ; T2.4 13.43,72.6 ; T2.4 16.47,72.6 ; 154.83,13.86 J7.2 154.83,11.54 ; 60.67,10.72 T14.3 ; T14.3 60.67,7.67 ; T14.3 63.71,10.72 ; T14.3 63.71,7.67 ; T12.1 160.31,14.68 ; T12.1 157.27,17.73 ; T12.1 157.27,14.68 ; T12.1 160.31,17.73 ; 53.23,11.54 J5.2 53.23,13.86 ; 53.23,140.86 J2.2 53.23,138.54 ; T14.2 58.71,10.72 ; T14.2 58.71,7.67 ; T14.2 55.67,7.67 ; T14.2 55.67,10.72 ; T14.4 63.71,14.68 ; T14.4 60.67,14.68 ; T14.4 63.71,17.73 ; T14.4 60.67,17.73 ; 111.47,144.73 T6.4 ; T6.4 114.51,141.68 ; T6.4 111.47,141.68 ; T6.4 114.51,144.73 ; 11.29,76.94 J1.2 13.61,76.94 ; 267.32,19.67 J11.3 269.64,19.67 ; J18.2 8.65,55.76 ; J18.2 8.65,49.91 ; J18.2 6.87,52.83 ; J18.2 10.43,52.83 ; 104.03,140.86 J3.2 104.03,138.54 ; 154.83,138.54 J4.2 154.83,140.86
  L2 w0.813: T12.1 160.31,17.73 ; T12.1 157.27,14.68 ; T12.1 157.27,17.73 ; T12.1 160.31,14.68 ; J1.2 13.61,76.94 ; J1.2 11.29,79.27 ; J1.2 11.29,76.94 ; J1.2 13.61,79.27 ; J2.2 53.23,140.86 ; J2.2 50.91,138.54 ; J2.2 53.23,138.54 ; J2.2 50.91,140.86 ; 101.71,13.86 J6.2 ; J6.2 101.71,11.54 ; J6.2 104.03,13.86 ; J6.2 104.03,11.54 ; T14.2 58.71,7.67 ; T14.2 55.67,7.67 ; T14.2 55.67,10.72 ; T14.2 58.71,10.72 ; 55.67,134.67 T4.2 ; T4.2 58.71,134.67 ; T4.2 58.71,137.72 ; T4.2 55.67,137.72 ; T6.1 109.51,141.68 ; T6.1 106.47,141.68 ; T6.1 109.51,144.73 ; T6.1 106.47,144.73 ; 60.67,137.72 T4.3 ; T4.3 63.71,137.72 ; T4.3 60.67,134.67 ; T4.3 63.71,134.67 ; J7.2 154.83,11.54 ; J7.2 152.51,11.54 ; J7.2 154.83,13.86 ; J7.2 152.51,13.86 ; 55.67,144.73 T4.1 ; T4.1 55.67,141.68 ; T4.1 58.71,144.73 ; T4.1 58.71,141.68 ; 195.29,141.68 T18.4 ; T18.4 198.33,144.73 ; T18.4 198.33,141.68 ; T18.4 195.29,144.73 ; 60.67,17.73 T14.4 ; T14.4 63.71,17.73 ; T14.4 63.71,14.68 ; T14.4 60.67,14.68 ; T6.3 114.51,134.67 ; T6.3 114.51,137.72 ; T6.3 111.47,134.67 ; T6.3 111.47,137.72 ; 208.07,17.73 T16.1 ; T16.1 211.11,14.68 ; T16.1 208.07,14.68 ; T16.1 211.11,17.73 ; T12.4 165.31,14.68 ; T12.4 162.27,17.73 ; T12.4 162.27,14.68 ; T12.4 165.31,17.73 ; 162.27,7.67 T12.3 ; T12.3 162.27,10.72 ; T12.3 165.31,10.72 ; T12.3 165.31,7.67 ; 157.27,10.72 T12.2 ; T12.2 160.31,10.72 ; T12.2 157.27,7.67 ; T12.2 160.31,7.67 ; 265.49,76.14 J13.11 265.49,73.72 ; T2.1 11.47,75.64 ; T2.1 8.42,72.6 ; T2.1 11.47,72.6 ; T2.1 8.42,75.64 ; J4.2 154.83,140.86 ; J4.2 154.83,138.54 ; J4.2 152.51,140.86 ; J4.2 152.51,138.54 ; 11.65,46.35 J18.3 ; J18.3 14.57,48.13 ; J18.3 11.65,49.91 ; J18.3 8.72,48.13 ; T14.1 58.71,17.73 ; T14.1 55.67,14.68 ; T14.1 58.71,14.68 ; T14.1 55.67,17.73 ; 267.32,21.99 J11.3 ; J11.3 267.32,19.67 ; J11.3 269.64,21.99 ; J11.3 269.64,19.67 ; T6.4 114.51,141.68 ; T6.4 111.47,141.68 ; T6.4 114.51,144.73 ; T6.4 111.47,144.73 ; 13.43,75.64 T2.4 ; T2.4 16.47,72.6 ; T2.4 13.43,72.6 ; T2.4 16.47,75.64 ; T8.3 165.31,134.67 ; T8.3 162.27,134.67 ; T8.3 165.31,137.72 ; T8.3 162.27,137.72 ; 157.27,141.68 T8.1 ; T8.1 160.31,144.73 ; T8.1 160.31,141.68 ; T8.1 157.27,144.73 ; T4.4 63.71,141.68 ; T4.4 63.71,144.73 ; T4.4 60.67,144.73 ; T4.4 60.67,141.68 ; T14.3 63.71,7.67 ; T14.3 60.67,10.72 ; T14.3 60.67,7.67 ; T14.3 63.71,10.72 ; 106.47,7.67 T10.2 ; T10.2 109.51,7.67 ; T10.2 109.51,10.72 ; T10.2 106.47,10.72 ; 106.47,14.68 T10.1 ; T10.1 109.51,17.73 ; T10.1 106.47,17.73 ; T10.1 109.51,14.68 ; 190.29,137.72 T18.2 ; T18.2 193.33,134.67 ; T18.2 190.29,134.67 ; T18.2 193.33,137.72 ; 208.07,10.72 T16.2 ; T16.2 208.07,7.67 ; T16.2 211.11,7.67 ; T16.2 211.11,10.72 ; T2.2 11.47,68.63 ; T2.2 8.42,65.59 ; T2.2 8.42,68.63 ; T2.2 11.47,65.59 ; 101.71,138.54 J3.2 ; J3.2 101.71,140.86 ; J3.2 104.03,140.86 ; J3.2 104.03,138.54 ; 111.47,10.72 T10.3 ; T10.3 114.51,10.72 ; T10.3 114.51,7.67 ; T10.3 111.47,7.67 ; T2.3 16.47,65.59 ; T2.3 16.47,68.63 ; T2.3 13.43,68.63 ; T2.3 13.43,65.59 ; T8.2 160.31,134.67 ; T8.2 157.27,137.72 ; T8.2 160.31,137.72 ; T8.2 157.27,134.67 ; T18.1 193.33,141.68 ; T18.1 193.33,144.73 ; T18.1 190.29,144.73 ; T18.1 190.29,141.68 ; 50.91,11.54 J5.2 ; J5.2 50.91,13.86 ; J5.2 53.23,11.54 ; J5.2 53.23,13.86 ; T16.3 216.11,10.72 ; T16.3 213.07,10.72 ; T16.3 213.07,7.67 ; T16.3 216.11,7.67 ; J18.2 10.43,52.83 ; J18.2 6.87,52.83 ; J18.2 8.65,55.76 ; J18.2 8.65,49.91 ; J21.2 269.77,32.28 ; J21.2 267.44,32.28 ; J21.2 269.77,29.95 ; T10.4 114.51,17.73 ; T10.4 111.47,14.68 ; T10.4 114.51,14.68 ; T10.4 111.47,17.73 ; T6.2 109.51,137.72 ; T6.2 109.51,134.67 ; T6.2 106.47,134.67 ; T6.2 106.47,137.72 ; T18.3 198.33,137.72 ; T18.3 198.33,134.67 ; T18.3 195.29,137.72 ; T18.3 195.29,134.67 ; T16.4 216.11,14.68 ; T16.4 213.07,14.68 ; T16.4 213.07,17.73 ; T16.4 216.11,17.73 ; T8.4 165.31,144.73 ; T8.4 162.27,144.73 ; T8.4 165.31,141.68 ; T8.4 162.27,141.68 ; J9.2 203.09,140.86 ; J9.2 200.77,140.86 ; J9.2 200.77,138.54 ; J9.2 203.09,138.54 ; 203.31,13.86 J8.2 ; J8.2 205.63,11.54 ; J8.2 203.31,11.54 ; J8.2 205.63,13.86
  L3 w0.813: 208.07,7.67 T16.2 ; T16.2 208.07,10.72 ; T16.2 211.11,7.67 ; T16.2 211.11,10.72 ; 203.31,11.54 J8.2 ; J8.2 203.31,13.86 ; J8.2 205.63,11.54 ; J8.2 205.63,13.86 ; T4.3 63.71,137.72 ; T4.3 60.67,134.67 ; T4.3 63.71,134.67 ; T4.3 60.67,137.72 ; 111.47,14.68 T10.4 ; T10.4 114.51,14.68 ; T10.4 111.47,17.73 ; T10.4 114.51,17.73 ; T14.1 58.71,17.73 ; T14.1 58.71,14.68 ; T14.1 55.67,17.73 ; T14.1 55.67,14.68 ; 195.29,144.73 T18.4 ; T18.4 195.29,141.68 ; T18.4 198.33,144.73 ; T18.4 198.33,141.68 ; J11.3 269.64,21.99 ; J11.3 269.64,19.67 ; J11.3 267.32,21.99 ; 162.27,141.68 T8.4 ; T8.4 165.31,144.73 ; T8.4 165.31,141.68 ; T8.4 162.27,144.73 ; 157.27,144.73 T8.1 ; T8.1 160.31,141.68 ; T8.1 160.31,144.73 ; T8.1 157.27,141.68 ; 111.47,10.72 T10.3 ; T10.3 114.51,10.72 ; T10.3 114.51,7.67 ; T10.3 111.47,7.67 ; 55.67,10.72 T14.2 ; T14.2 55.67,7.67 ; T14.2 58.71,7.67 ; T14.2 58.71,10.72 ; T6.4 114.51,144.73 ; T6.4 111.47,144.73 ; T6.4 114.51,141.68 ; T6.4 111.47,141.68 ; T14.3 63.71,10.72 ; T14.3 63.71,7.67 ; T14.3 60.67,7.67 ; T14.3 60.67,10.72 ; J18.3 11.65,49.91 ; J18.3 14.57,48.13 ; J18.3 11.65,46.35 ; J18.3 8.72,48.13 ; 157.27,134.67 T8.2 ; T8.2 157.27,137.72 ; T8.2 160.31,137.72 ; T8.2 160.31,134.67 ; 11.29,76.94 J1.2 ; J1.2 13.61,76.94 ; J1.2 13.61,79.27 ; J1.2 11.29,79.27 ; 195.29,137.72 T18.3 ; T18.3 198.33,134.67 ; T18.3 195.29,134.67 ; T18.3 198.33,137.72 ; T2.2 11.47,65.59 ; T2.2 11.47,68.63 ; T2.2 8.42,68.63 ; T2.2 8.42,65.59 ; T10.1 109.51,14.68 ; T10.1 106.47,17.73 ; T10.1 109.51,17.73 ; T10.1 106.47,14.68 ; 50.91,138.54 J2.2 ; J2.2 50.91,140.86 ; J2.2 53.23,138.54 ; J2.2 53.23,140.86 ; T6.3 114.51,137.72 ; T6.3 114.51,134.67 ; T6.3 111.47,134.67 ; T6.3 111.47,137.72 ; 50.91,13.86 J5.2 ; J5.2 53.23,11.54 ; J5.2 53.23,13.86 ; J5.2 50.91,11.54 ; 152.51,138.54 J4.2 ; J4.2 152.51,140.86 ; J4.2 154.83,138.54 ; J4.2 154.83,140.86 ; 213.07,14.68 T16.4 ; T16.4 216.11,17.73 ; T16.4 213.07,17.73 ; T16.4 216.11,14.68 ; T12.4 165.31,14.68 ; T12.4 162.27,14.68 ; T12.4 162.27,17.73 ; T12.4 165.31,17.73 ; 13.43,68.63 T2.3 ; T2.3 13.43,65.59 ; T2.3 16.47,68.63 ; T2.3 16.47,65.59 ; 157.27,7.67 T12.2 ; T12.2 160.31,7.67 ; T12.2 157.27,10.72 ; T12.2 160.31,10.72 ; 60.67,14.68 T14.4 ; T14.4 63.71,14.68 ; T14.4 60.67,17.73 ; T14.4 63.71,17.73 ; T16.1 211.11,14.68 ; T16.1 211.11,17.73 ; T16.1 208.07,14.68 ; T16.1 208.07,17.73 ; T6.1 109.51,141.68 ; T6.1 106.47,141.68 ; T6.1 106.47,144.73 ; T6.1 109.51,144.73 ; J18.2 8.65,55.76 ; J18.2 10.43,52.83 ; J18.2 8.65,49.91 ; J18.2 6.87,52.83 ; 190.29,137.72 T18.2 ; T18.2 190.29,134.67 ; T18.2 193.33,137.72 ; T18.2 193.33,134.67 ; J7.2 154.83,11.54 ; J7.2 154.83,13.86 ; J7.2 152.51,13.86 ; J7.2 152.51,11.54 ; 162.27,137.72 T8.3 ; T8.3 162.27,134.67 ; T8.3 165.31,137.72 ; T8.3 165.31,134.67 ; 101.71,13.86 J6.2 ; J6.2 104.03,13.86 ; J6.2 104.03,11.54 ; J6.2 101.71,11.54 ; T16.3 216.11,10.72 ; T16.3 213.07,7.67 ; T16.3 213.07,10.72 ; T16.3 216.11,7.67 ; T12.1 160.31,14.68 ; T12.1 157.27,17.73 ; T12.1 157.27,14.68 ; T12.1 160.31,17.73 ; 106.47,137.72 T6.2 ; T6.2 106.47,134.67 ; T6.2 109.51,134.67 ; T6.2 109.51,137.72 ; J3.2 104.03,140.86 ; J3.2 101.71,140.86 ; J3.2 104.03,138.54 ; J3.2 101.71,138.54 ; T4.1 58.71,141.68 ; T4.1 55.67,144.73 ; T4.1 55.67,141.68 ; T4.1 58.71,144.73 ; T4.2 58.71,134.67 ; T4.2 55.67,137.72 ; T4.2 55.67,134.67 ; T4.2 58.71,137.72 ; 8.42,75.64 T2.1 ; T2.1 8.42,72.6 ; T2.1 11.47,72.6 ; T2.1 11.47,75.64 ; 190.29,144.73 T18.1 ; T18.1 193.33,141.68 ; T18.1 193.33,144.73 ; T18.1 190.29,141.68 ; T2.4 16.47,72.6 ; T2.4 16.47,75.64 ; T2.4 13.43,75.64 ; T2.4 13.43,72.6 ; 162.27,10.72 T12.3 ; T12.3 162.27,7.67 ; T12.3 165.31,10.72 ; T12.3 165.31,7.67 ; T10.2 109.51,7.67 ; T10.2 106.47,7.67 ; T10.2 106.47,10.72 ; T10.2 109.51,10.72 ; 200.77,140.86 J9.2 ; J9.2 203.09,140.86 ; J9.2 203.09,138.54 ; J9.2 200.77,138.54 ; T4.4 63.71,144.73 ; T4.4 63.71,141.68 ; T4.4 60.67,141.68 ; T4.4 60.67,144.73 ; 269.77,29.95 J21.2 269.77,32.28
  BOTTOM w0.305: C134.1 48.9,102.74 v1(48.39,103.25) ; C135.1 52.7,49.66 v1(53.21,49.15) ; C133.1 150.5,102.74 v1(149.99,103.25) ; U10.13 v2(237.74,79.77) ; R65.1 236.22,69.27 v2(236.47,69.02) ; C136.1 154.31,49.66 v1(154.81,49.15) ; U10.11 234.6,79.13 v2(234.92,79.45) 234.6,79.77 U10.12 ; C129.1 v2(237.49,69.02) ; v1(104.01,49.15) 103.5,49.66 C137.1 ; C128.1 v2(238.76,69.02) ; C151.2 247.46,77.82 247.85,78.21 v2(248.26,78.21) ; C132.1 99.69,102.74 v1(99.19,103.25) ; C130.1 v2(233.68,69.02)
  BOTTOM w0.813: T10.2 109.51,7.67 ; T10.2 109.51,10.72 ; T10.2 106.47,10.72 ; T10.2 106.47,7.67 ; T6.4 114.51,144.73 ; T6.4 111.47,141.68 ; T6.4 111.47,144.73 ; T6.4 114.51,141.68 ; T16.3 216.11,10.72 ; T16.3 216.11,7.67 ; T16.3 213.07,10.72 ; T16.3 213.07,7.67 ; T2.2 11.47,68.63 ; T2.2 11.47,65.59 ; T2.2 8.42,65.59 ; T2.2 8.42,68.63 ; T4.3 63.71,137.72 ; T4.3 63.71,134.67 ; T4.3 60.67,134.67 ; T4.3 60.67,137.72 ; 200.77,140.86 J9.2 ; J9.2 203.09,140.86 ; J9.2 203.09,138.54 ; J9.2 200.77,138.54 ; J18.3 11.65,49.91 ; J18.3 8.72,48.13 ; J18.3 11.65,46.35 ; J18.3 14.57,48.13 ; 157.27,14.68 T12.1 ; T12.1 160.31,14.68 ; T12.1 157.27,17.73 ; T12.1 160.31,17.73 ; 213.07,17.73 T16.4 ; T16.4 213.07,14.68 ; T16.4 216.11,17.73 ; T16.4 216.11,14.68 ; 106.47,141.68 T6.1 ; T6.1 106.47,144.73 ; T6.1 109.51,141.68 ; T6.1 109.51,144.73 ; 55.67,17.73 T14.1 ; T14.1 58.71,17.73 ; T14.1 58.71,14.68 ; T14.1 55.67,14.68 ; 8.42,75.64 T2.1 ; T2.1 11.47,72.6 ; T2.1 8.42,72.6 ; T2.1 11.47,75.64 ; 106.47,134.67 T6.2 ; T6.2 109.51,134.67 ; T6.2 106.47,137.72 ; T6.2 109.51,137.72 ; 55.67,7.67 T14.2 ; T14.2 55.67,10.72 ; T14.2 58.71,7.67 ; T14.2 58.71,10.72 ; J6.2 104.03,11.54 ; J6.2 104.03,13.86 ; J6.2 101.71,13.86 ; J6.2 101.71,11.54 ; 203.31,13.86 J8.2 ; J8.2 205.63,11.54 ; J8.2 205.63,13.86 ; J8.2 203.31,11.54 ; 111.47,14.68 T10.4 ; T10.4 111.47,17.73 ; T10.4 114.51,14.68 ; T10.4 114.51,17.73 ; 190.29,137.72 T18.2 ; T18.2 190.29,134.67 ; T18.2 193.33,134.67 ; T18.2 193.33,137.72 ; T18.3 198.33,134.67 ; T18.3 195.29,134.67 ; T18.3 198.33,137.72 ; T18.3 195.29,137.72 ; 195.29,141.68 T18.4 ; T18.4 195.29,144.73 ; T18.4 198.33,141.68 ; T18.4 198.33,144.73 ; 162.27,141.68 T8.4 ; T8.4 165.31,141.68 ; T8.4 162.27,144.73 ; T8.4 165.31,144.73 ; T10.1 109.51,14.68 ; T10.1 106.47,17.73 ; T10.1 109.51,17.73 ; T10.1 106.47,14.68 ; J21.2 269.77,29.95 ; J21.2 267.44,32.28 ; J21.2 269.77,32.28 ; J18.2 10.43,52.83 ; J18.2 8.65,49.91 ; J18.2 6.87,52.83 ; J18.2 8.65,55.76 ; 267.32,19.67 J11.3 ; J11.3 267.32,21.99 ; J11.3 269.64,21.99 ; J11.3 269.64,19.67 ; 101.71,138.54 J3.2 ; J3.2 101.71,140.86 ; J3.2 104.03,138.54 ; J3.2 104.03,140.86 ; 13.43,65.59 T2.3 ; T2.3 16.47,65.59 ; T2.3 16.47,68.63 ; T2.3 13.43,68.63 ; T6.3 114.51,134.67 ; T6.3 114.51,137.72 ; T6.3 111.47,137.72 ; T6.3 111.47,134.67 ; 60.67,144.73 T4.4 ; T4.4 63.71,144.73 ; T4.4 63.71,141.68 ; T4.4 60.67,141.68 ; T12.2 160.31,7.67 ; T12.2 157.27,7.67 ; T12.2 157.27,10.72 ; T12.2 160.31,10.72 ; T16.1 211.11,14.68 ; T16.1 208.07,14.68 ; T16.1 211.11,17.73 ; T16.1 208.07,17.73 ; 208.07,7.67 T16.2 ; T16.2 211.11,10.72 ; T16.2 208.07,10.72 ; T16.2 211.11,7.67 ; 162.27,137.72 T8.3 ; T8.3 162.27,134.67 ; T8.3 165.31,137.72 ; T8.3 165.31,134.67 ; T8.1 160.31,144.73 ; T8.1 157.27,141.68 ; T8.1 160.31,141.68 ; T8.1 157.27,144.73 ; J7.2 154.83,11.54 ; J7.2 154.83,13.86 ; J7.2 152.51,11.54 ; J7.2 152.51,13.86 ; 190.29,144.73 T18.1 ; T18.1 193.33,144.73 ; T18.1 193.33,141.68 ; T18.1 190.29,141.68 ; J5.2 53.23,11.54 ; J5.2 50.91,13.86 ; J5.2 53.23,13.86 ; J5.2 50.91,11.54 ; J1.2 13.61,79.27 ; J1.2 11.29,76.94 ; J1.2 13.61,76.94 ; J1.2 11.29,79.27 ; 60.67,14.68 T14.4 ; T14.4 60.67,17.73 ; T14.4 63.71,14.68 ; T14.4 63.71,17.73 ; T10.3 114.51,7.67 ; T10.3 111.47,10.72 ; T10.3 111.47,7.67 ; T10.3 114.51,10.72 ; J4.2 154.83,138.54 ; J4.2 152.51,140.86 ; J4.2 152.51,138.54 ; J4.2 154.83,140.86 ; 162.27,7.67 T12.3 ; T12.3 162.27,10.72 ; T12.3 165.31,7.67 ; T12.3 165.31,10.72 ; T4.2 58.71,134.67 ; T4.2 58.71,137.72 ; T4.2 55.67,137.72 ; T4.2 55.67,134.67 ; 60.67,10.72 T14.3 ; T14.3 63.71,10.72 ; T14.3 60.67,7.67 ; T14.3 63.71,7.67 ; 162.27,17.73 T12.4 ; T12.4 165.31,14.68 ; T12.4 162.27,14.68 ; T12.4 165.31,17.73 ; 50.91,140.86 J2.2 ; J2.2 50.91,138.54 ; J2.2 53.23,140.86 ; J2.2 53.23,138.54 ; 13.43,75.64 T2.4 ; T2.4 16.47,75.64 ; T2.4 16.47,72.6 ; T2.4 13.43,72.6 ; 55.67,141.68 T4.1 ; T4.1 55.67,144.73 ; T4.1 58.71,141.68 ; T4.1 58.71,144.73 ; T8.2 160.31,137.72 ; T8.2 157.27,137.72 ; T8.2 160.31,134.67 ; T8.2 157.27,134.67
  vias: v1(48.13,102.62) v1(50.2,101.9) v1(50.2,51.5) v1(50.2,51) v1(50.2,50.5) v1(50.5,102.2) v1(50.5,51.25) v1(50.5,50.2) v1(50.8,101.9) v1(50.8,101.4) v1(50.8,100.9) v1(50.8,51.5) v1(50.8,51) v1(50.8,50.5) v1(51.1,102.2) v1(51.1,101.15) v1(51.1,50.2) v1(51.4,101.9) v1(51.4,101.4) v1(51.4,100.9) v1(51.4,50.5) v1(53.47,49.78) v1(98.93,102.62) v1(101,101.9) v1(101,51.5) v1(101,51) v1(101,50.5) v1(101.3,102.2) v1(101.3,51.25) v1(101.3,50.2) v1(101.6,101.9) v1(101.6,101.4) v1(101.6,100.9) v1(101.6,51.5) v1(101.6,51) v1(101.6,50.5) v1(101.9,102.2) v1(101.9,101.15) v1(101.9,50.2) v1(102.2,101.9) v1(102.2,101.4) v1(102.2,100.9) v1(102.2,50.5) v1(104.27,49.78) v1(149.73,102.62) v1(151.8,101.9) v1(151.8,51.5) v1(151.8,51) v1(151.8,50.5) v1(152.1,102.2) v1(152.1,51.25) v1(152.1,50.2) v1(152.4,101.9) v1(152.4,101.4) v1(152.4,100.9) v1(152.4,51.5) v1(152.4,51) v1(152.4,50.5) v1(152.7,102.2) v1(152.7,101.15) v1(152.7,50.2) v1(153,101.9) v1(153,101.4) v1(153,100.9) v1(153,50.5) v1(155.07,49.78) v1(201.63,99.36) v1(201.65,102.62) v1(201.68,102.34) v1(201.65,102.03) v1(201.65,101.27) v1(201.65,100.74) v1(201.65,100.2) v1(201.9,102.62) v1(201.9,102.06) v1(201.88,100.97) v1(201.88,100.46) v1(201.93,99.52) v1(201.98,102.34) v1(202.11,101.27) v1(202.08,100.74) v1(202.08,100.2) v1(202.23,102.62) v1(202.23,102.06) v1(202.21,99.36) v1(202.31,100.99) v1(202.31,100.48) v1(202.54,101.27) v1(202.5,100.75) v1(202.54,100.2) v1(202.74,100.99) v1(202.74,100.48) v1(202.97,101.27) v1(202.97,100.74) v1(203,100.2) v1(202.97,52.2) v1(202.97,51.66) v1(202.97,51.1) v1(203.2,100.99) v1(203.2,100.48) v1(203.2,51.92) v1(203.2,51.41) v1(203.43,101.3) v1(203.43,100.74) v1(203.43,100.2) v1(203.4,52.2) v1(203.43,51.66) v1(203.43,51.13) v1(203.66,51.92) v1(203.66,51.41) v1(203.86,52.2) v1(203.9,51.65) v1(203.86,51.13) v1(204.09,51.92) v1(204.09,51.41) v1(204.19,53.04) v1(204.17,50.34) v1(204.17,49.78) v1(204.32,52.2) v1(204.32,51.66) v1(204.29,51.13) v1(204.42,50.06) v1(204.47,52.88) v1(204.52,51.94) v1(204.52,51.44) v1(204.5,50.34) v1(204.5,49.78) v1(204.75,52.2) v1(204.75,51.66) v1(204.75,51.13) v1(204.75,50.37) v1(204.72,50.06) v1(204.75,49.78) v1(204.77,53.04) v2(7.62,101.6) v2(15.24,25.4) v2(17.78,142.24) v2(17.78,132.08) v2(17.78,121.92) v2(17.78,111.76) v2(17.78,40.64) v2(38.1,101.6) v2(45.01,105.92) v2(45.01,105.03) v2(45.01,104.14) v2(45.01,99.57) v2(45.01,98.68) v2(45.01,97.79) v2(46.02,105.92) v2(46.02,105.03) v2(46.02,104.14) v2(46.02,99.57) v2(46.02,98.68) v2(46.02,97.79) v2(46.48,53.72) v2(46.74,54.61) v2(46.74,47.88) v2(46.81,46.38) v2(47.5,53.72) v2(47.62,47.88) v2(47.78,46.38) v2(47.88,54.61) v2(48.13,55.5) v2(48.74,46.38) v2(49.15,55.5) v2(52.83,106.02) v2(53.8,106.02) v2(53.82,98.27) v2(53.82,97.38) v2(53.82,96.49) v2(53.95,104.52) v2(54.76,106.02) v2(54.84,104.52) v2(54.84,98.27) v2(54.84,97.38) v2(54.84,96.49) v2(55.55,54.61) v2(55.55,53.72) v2(55.55,52.83) v2(55.55,48.26) v2(55.55,47.37) v2(55.55,46.48) v2(56.57,54.61) v2(56.57,53.72) v2(56.57,52.83) v2(56.57,48.26) v2(56.57,47.37) v2(56.57,46.48) v2(66.04,53.34) v2(66.04,40.64) v2(66.04,25.4) v2(68.58,129.54) v2(68.58,106.68) v2(95.81,105.92) v2(95.81,105.03) v2(95.81,104.14) v2(95.81,99.57) v2(95.81,98.68) v2(95.81,97.79) v2(96.82,105.92) v2(96.82,105.03) v2(96.82,104.14) v2(96.82,99.57) v2(96.82,98.68) v2(96.82,97.79) v2(97.28,53.72) v2(97.54,54.61) v2(97.54,47.88) v2(97.61,46.38) v2(98.3,53.72) v2(98.42,47.88) v2(98.58,46.38) v2(98.68,54.61) v2(98.93,55.5) v2(99.54,46.38) v2(99.95,55.5) v2(103.63,106.02) v2(104.6,106.02) v2(104.62,98.27) v2(104.62,97.38) v2(104.62,96.49) v2(104.75,104.52) v2(105.56,106.02) v2(105.64,104.52) v2(105.64,98.27) v2(105.64,97.38) v2(105.64,96.49) v2(106.35,54.61) v2(106.35,53.72) v2(106.35,52.83) v2(106.35,48.26) v2(106.35,47.37) v2(106.35,46.48) v2(107.37,54.61) v2(107.37,53.72) v2(107.37,52.83) v2(107.37,48.26) v2(107.37,47.37) v2(107.37,46.48) v2(116.84,129.54) v2(116.84,106.68) v2(116.84,53.34) v2(116.84,43.18) v2(116.84,27.94) v2(146.61,105.92) v2(146.61,105.03) v2(146.61,104.14) v2(146.61,99.57) v2(146.61,98.68) v2(146.61,97.79) v2(147.62,105.92) v2(147.62,105.03) v2(147.62,104.14) v2(147.62,99.57) v2(147.62,98.68) v2(147.62,97.79) v2(148.08,53.72) v2(148.34,54.61) v2(148.34,47.88) v2(148.41,46.38) v2(149.1,53.72) v2(149.22,47.88) v2(149.38,46.38) v2(149.48,54.61) v2(149.73,55.5) v2(150.34,46.38) v2(150.75,55.5) v2(154.43,106.02) v2(155.4,106.02) v2(155.42,98.27) v2(155.42,97.38) v2(155.42,96.49) v2(155.55,104.52) v2(156.36,106.02) v2(156.44,104.52) v2(156.44,98.27) v2(156.44,97.38) v2(156.44,96.49) v2(157.15,54.61) v2(157.15,53.72) v2(157.15,52.83) v2(157.15,48.26) v2(157.15,47.37) v2(157.15,46.48) v2(158.17,54.61) v2(158.17,53.72) v2(158.17,52.83) v2(158.17,48.26) v2(158.17,47.37) v2(158.17,46.48) v2(162.56,124.46) v2(162.56,116.84) v2(162.56,106.68) v2(167.64,53.34) v2(167.64,40.64) v2(167.64,25.4) v2(172.72,144.78) v2(172.72,134.62) v2(172.72,124.46) v2(172.72,116.84) v2(172.72,106.68) v2(180.34,144.78) v2(180.34,134.62) v2(180.34,124.46) v2(180.34,116.84) v2(190.5,124.46) v2(190.5,116.84) v2(197.82,109.47) v2(197.82,108.89) v2(197.82,108.31) v2(197.82,107.72) v2(197.82,107.14) v2(197.82,106.55) v2(197.82,105.97) v2(197.82,105.38) v2(198.4,109.47) v2(198.4,108.89) v2(198.4,108.31) v2(198.4,107.72) v2(198.4,107.14) v2(198.4,106.55) v2(198.4,105.97) v2(198.4,105.38) v2(198.98,109.47) v2(198.98,108.89) v2(198.98,108.31) v2(198.98,107.72) v2(198.98,107.14) v2(198.98,106.55) v2(198.98,105.97) v2(198.98,105.38) v2(199.97,97.1) v2(199.97,96.22) v2(199.97,95.33) v2(199.97,94.44) v2(200.86,97.1) v2(200.86,96.22) v2(200.86,95.33) v2(200.86,94.44) v2(205.54,57.96) v2(205.54,57.07) v2(205.54,56.18) v2(205.54,55.3) v2(206.43,57.96) v2(206.43,57.07) v2(206.43,56.18) v2(206.43,55.3) v2(207.42,47.02) v2(207.42,46.43) v2(207.42,45.85) v2(207.42,45.26) v2(207.42,44.68) v2(207.42,44.09) v2(207.42,43.51) v2(207.42,42.93) v2(208,47.02) v2(208,46.43) v2(208,45.85) v2(208,45.26) v2(208,44.68) v2(208,44.09) v2(208,43.51) v2(208,42.93) v2(208.58,47.02) v2(208.58,46.43) v2(208.58,45.85) v2(208.58,45.26) v2(208.58,44.68) v2(208.58,44.09) v2(208.58,43.51) v2(208.58,42.93) v2(213.36,33.02) v2(213.36,22.86) v2(231.14,144.78) v2(231.14,134.62) v2(231.14,124.46) v2(231.14,33.02) v2(231.14,22.86) v2(231.14,10.16) v2(233.68,91.44) v2(237.49,49.53) v2(237.49,48.26) v2(237.49,46.99) v2(237.49,45.72) v2(238.12,50.8) v2(238.76,49.53) v2(238.76,48.26) v2(238.76,46.99) v2(238.76,45.72) v2(246.38,144.78) v2(246.38,134.62) v2(246.38,124.46) v2(246.38,10.16) v2(254,91.44) v2(259.08,144.78) v2(265.23,18.06)
PVIN: length 45.3
  TOP w0.813: 12.87,52.83 J18.1 ; J18.1 16.43,52.83 ; J18.1 14.65,56.01 ; 13.43,90.38 T1.4 ; T1.4 16.47,90.38 ; T1.4 16.47,93.42 ; T1.4 13.43,93.42 ; T1.1 11.47,93.42 ; T1.1 8.42,93.42 ; T1.1 8.42,90.38 ; T1.1 11.47,90.38 ; 13.43,86.41 T1.3 ; T1.3 16.47,86.41 ; T1.3 13.43,83.37 ; T1.3 16.47,83.37 ; T1.2 11.47,86.41 ; T1.2 8.42,86.41 ; T1.2 8.42,83.37 ; T1.2 11.47,83.37 ; 13.91,82.11 J1.1 10.98,82.11
  vias: v1(49.3,100.71) v1(49.68,100.71) v1(49.68,100.3) v1(49.68,99.87) v1(49.68,99.44) v1(50,100.7) v1(50,100.3) v1(50.04,99.87) v1(50.04,99.44) v1(51.56,52.96) v1(51.56,52.53) v1(51.6,52.1) v1(51.6,51.7) v1(51.92,52.96) v1(51.92,52.53) v1(51.92,52.1) v1(51.92,51.69) v1(52.3,51.69) v1(100.1,100.71) v1(100.48,100.71) v1(100.48,100.3) v1(100.48,99.87) v1(100.48,99.44) v1(100.8,100.7) v1(100.8,100.3) v1(100.84,99.87) v1(100.84,99.44) v1(102.36,52.96) v1(102.36,52.53) v1(102.4,52.1) v1(102.4,51.7) v1(102.72,52.96) v1(102.72,52.53) v1(102.72,52.1) v1(102.72,51.69) v1(103.1,51.69) v1(150.9,100.71) v1(151.28,100.71) v1(151.28,100.3) v1(151.28,99.87) v1(151.28,99.44) v1(151.6,100.7) v1(151.6,100.3) v1(151.64,99.87) v1(151.64,99.44) v1(153.16,52.96) v1(153.16,52.53) v1(153.2,52.1) v1(153.2,51.7) v1(153.52,52.96) v1(153.52,52.53) v1(153.52,52.1) v1(153.52,51.69) v1(153.9,51.69) v1(201.57,53.06) v1(201.57,52.04) v1(201.57,51.54) v1(201.57,51.1) v1(201.85,52.88) v1(201.88,52.22) v1(201.88,51.79) v1(201.88,51.36) v1(202.18,53.06) v1(202.16,52.04) v1(202.16,51.54) v1(202.16,51.1) v1(204.24,101.3) v1(204.24,100.86) v1(204.24,100.36) v1(204.22,99.34) v1(204.52,101.04) v1(204.52,100.61) v1(204.52,100.18) v1(204.55,99.52) v1(204.83,101.3) v1(204.83,100.86) v1(204.83,100.36) v1(204.83,99.34) v2(200.38,57.96) v2(200.38,57.07) v2(200.38,56.18) v2(200.38,55.3) v2(201.27,57.96) v2(201.27,57.07) v2(201.27,56.18) v2(201.27,55.3) v2(205.13,97.1) v2(205.13,96.22) v2(205.13,95.33) v2(205.13,94.44) v2(206.02,97.1) v2(206.02,96.22) v2(206.02,95.33) v2(206.02,94.44) v2(232.41,52.45) v2(232.41,50.93) v2(232.41,49.28) v2(232.41,47.75) v2(233.68,51.69) v2(233.68,50.04) v2(233.68,48.39)
VCC3: length 1.9
  TOP w0.305: U3.10 v1(149.86,101.87)
  BOTTOM w0.305: v1(149.86,101.87) 150.08,101.66 C133.2
CTRL: length 46.7
  BOTTOM w0.305: SW2.2 275.77,56.69 275.77,83.06 271.2,87.63 J13.2
EN1: length 300.2
  TOP w0.305: v2(263.16,114.81) SW3.1 270.1,114.81 271.86,113.06 271.86,95.78 277.62,90.02 277.62,73.15 J13.20 ; v2(56.03,99.75) 54.66,101.12 53.39,101.12 53.18,101.33 U1.3
  L3 w0.305: v2(56.03,99.75) 65.48,99.75 82.8,82.42 v2(215.65,82.42)
  BOTTOM w0.305: v2(263.16,114.81) 240.61,114.81 215.65,89.84 v2(215.65,82.42)
EN2: length 234.8
  TOP w0.305: U2.3 103.98,101.33 104.19,101.12 105.46,101.12 v2(106.83,99.75) ; v2(263.16,112.27) SW3.2 269.98,112.27 271.07,111.18 271.07,95.25 276.53,89.79 276.53,74.6 J13.18
  L3 w0.305: v2(218.74,86.18) 139.73,86.18 126.16,99.75 v2(106.83,99.75)
  BOTTOM w0.305: v2(218.74,86.18) 244.83,112.27 v2(263.16,112.27)
EN3: length 185.9
  TOP w0.305: U3.3 154.78,101.33 154.94,101.17 156.21,101.17 v2(157.63,99.75) ; J13.16 275.46,76.07 275.46,89.59 270.28,94.77 270.28,108.43 268.99,109.73 SW3.3 v2(263.14,109.73)
  L3 w0.305: v2(157.63,99.75) 177.22,99.75 185.93,91.03 v2(220.65,91.03)
  BOTTOM w0.305: v2(263.14,109.73) 246.33,109.73 220.85,84.25 218.41,84.25 217.47,85.19 217.47,87.86 v2(220.65,91.03)
EN4: length 289.7
  TOP w0.305: v2(46.43,52.63) 46.43,52.15 47.28,51.29 48.2,51.29 48.42,51.07 U4.3 ; J13.14 274.29,77.44 274.29,89.38 269.44,94.23 269.44,106.48 268.73,107.19 SW3.4
  L3 w0.305: v2(46.43,52.63) 45.72,53.34 45.72,54.99 64.03,73.3 v2(216.99,73.3)
  BOTTOM w0.305: J13.14 267.94,71.09 263.98,71.09 258.27,65.38 219.96,65.38 216.99,68.35 v2(216.99,73.3)
EN5: length 225.5
  TOP w0.305: U5.3 99.32,51.07 99.01,51.38 97.99,51.38 97.23,52.15 v2(97.23,52.63) ; J13.12 273.23,78.92 273.23,89.1 268.71,93.62 268.71,103.71 267.77,104.65 SW3.5
  L3 w0.305: v2(97.23,52.63) 96.47,53.39 96.47,54.84 110.92,69.29 210.9,69.29 212.8,67.39 v2(220.22,67.39)
  BOTTOM w0.305: J13.12 268,73.69 264.24,73.69 257.94,67.39 v2(220.22,67.39)
EN6: length 179.3
  TOP w0.305: J13.10 272.14,80.37 272.14,88.87 267.87,93.14 267.87,101.7 267.46,102.11 SW3.6 ; v2(148.03,52.63) 148.03,52.15 148.88,51.29 149.8,51.29 150.02,51.07 U6.3
  L3 w0.305: v2(148.03,52.63) 147.29,53.37 147.29,55.35 156.01,64.06 208.41,64.06 209.27,63.2 v2(220.12,63.2)
  BOTTOM w0.305: J13.10 270.97,75.74 270.97,64.08 270.08,63.2 v2(220.12,63.2)
EN7: length 83.7
  TOP w0.305: J13.8 271.09,81.86 271.09,88.52 267.06,92.56 267.06,99.34 266.83,99.57 SW3.7 v2(262.51,99.57) ; U7.3 206.29,100.88 207.11,100.05 v2(210.01,100.05)
  L3 w0.305: v2(262.51,99.57) 210.49,99.57 v2(210.01,100.05)
EN8: length 125.8
  TOP w0.305: J13.4 267.97,86.36 267.97,89.9 265.06,92.81 SW3.8 ; v2(196.01,53.72) 196.01,52.83 196.24,52.6 199.03,52.6 200.11,51.52 U8.3
  L3 w0.305: v2(220.01,60.07) 200.56,60.07 196.01,55.52 v2(196.01,53.72)
  BOTTOM w0.305: v2(220.01,60.07) 230.63,60.07 232.21,61.65 272.06,61.65 273.41,62.99 273.41,80.92 J13.4
LED1: length 23.2
  TOP w0.229: U11.12 248.53,75.4 248.89,75.03 248.89,73.3 v2(251.21,70.99) 251.94,70.26 252.54,70.26 D1.1
  BOTTOM w0.305: U10.21 240.39,74.57 240.64,74.32 240.64,72.69 241.71,71.63 250.57,71.63 v2(251.21,70.99)
LED2: length 21.4
  TOP w0.229: D2.1 252.22,71.5 v2(251.21,72.52) 249.38,74.35 249.38,75.23 248.81,75.8 U11.13
  BOTTOM w0.305: v2(251.21,72.52) 250.55,73.18 241.81,73.18 241.17,73.81 241.17,74.73 240.68,75.22 U10.20
